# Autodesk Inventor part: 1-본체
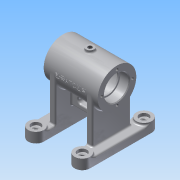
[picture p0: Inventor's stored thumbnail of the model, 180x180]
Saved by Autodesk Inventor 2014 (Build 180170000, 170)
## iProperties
Created: 2015-11
Part Number: 1-본체
Material: 알루미늄 6061
Document SubType Name: Modeling
Designer: 103-15
Density: 2.71 g/cm^3
Appearance: 알루미늄 - 평지
Mass: 357.75 g
Surface Area: 463.164 cm^2
Volume: 132.011 cm^3
Author: 103-15
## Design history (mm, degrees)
sketch "스케치1"
  geometry: L1 (-35, 0)-(35, 0); L2 (-35, 0)-(-35, 25); L3 (-35, 25)-(35, 25); L4 (35, 25)-(35, 0); L5 (-21, 0)-(-21, 21); L6 (-21, 21)-(21, 21); L7 (21, 21)-(21, 0); 3 further points
  constraints: 14 end point, 4 perpendicular, 2 midpoint, 2 parallel, 2 point on line, 1 coincident, 1 horizontal, 1 vertical alignment
  dimensions: "d0" = 70 distance of L1.start L1.end; "d1" = 50 diameter of L3 L1; "d16" = 42 diameter of L6 L1; "d17" = 42 distance between parallel lines of L7 L5
revolve "회전1" sketch "스케치1" stored, may be unused: angle "d2" = 90 deg
node "작업 평면1"
sketch "스케치2"
  geometry: L1 (30, -50)-(-30, -50); L2 (-40, -40)-(-40, 40); L3 (-30, 50)-(30, 50); L4 (40, 40)-(40, -40); L5 (40, -50)-(-40, 50); L6 (-40, -50)-(40, 50); L7 (-20, 40)-(-20, -40); L8 (20, -40)-(20, 40); A1 r 10 centre (-30, 40) between (-40, 40) and (-30, 50); A2 r 10 centre (-30, -40) between (-30, -50) and (-40, -40); A3 r 10 centre (30, -40) between (40, -40) and (30, -50); A4 r 10 centre (30, 40) between (30, 50) and (40, 40); 1 further point
  constraints: 16 end point, 12 point on circle, 11 tangent, 8 point on line, 4 centre point, 3 equal radius, 3 parallel, 2 midpoint, 1 horizontal, 1 perpendicular
  dimensions: "d4" = 100 distance of L6.start L5.end; "d5" = 80 distance of L5.start L6.start; "d6" = 10 radius of A1
extrude "돌출1" join sketch "스케치2" distance "d7" = 10; taper "d8" = 0 deg
extrude "돌출2" join sketch "스케치2" distance "d9" = 13; taper "d10" = 0 deg
node "작업 평면3"
sketch "스케치3"
  geometry: L1 (0, 10)-(80, 10) reference; L2 (15, 68)-(15, 10); L3 (65, 68)-(65, 10); A1 r 25 centre (40, 68) between (15, 68) and (65, 68) reference; 1 further point
  constraints: 4 end point, 2 perpendicular, 2 point on circle, 2 point on line, 2 tangent
extrude "돌출3" join sketch "스케치3" distance "d12" = 8; taper "d13" = 0 deg
node "작업 평면4"
hole "구멍1" diameter "d20" = 28; stored, may be unused: countersink angle "d24" = 90 deg, drill point angle "d26" = 118 deg; dims "d18" = 10, "d19" = 10, "d21" = 6, "d22" = 32, "d23" = 12, "d25" = 8
sketch "스케치4"
  geometry: C1 r 16 at (0, 0) reference; 1 further point
  constraints: 1 horizontal alignment
  dimensions: "d27" = 20 distance of C1.centre point (-20, 0)
hole "구멍2" sketch "스케치4" at (-20, 0) diameter "d28" = 3.242; stored, may be unused: countersink angle "d32" = 90 deg, drill point angle "d34" = 118 deg; dims "d29" = 8, "d30" = 32, "d31" = 12, "d33" = 10
node "작업 평면5"
sketch "스케치5"
  geometry: C1 r 10 at (0, 0) reference; C2 r 10 at (-60, 80) reference; C3 r 10 at (0, 80) reference; C4 r 10 at (-60, 0) reference; 5 further points
  constraints: 4 coincident
hole "구멍3" sketch "스케치5" at (-60, 80), (0, 80), (-60, 0), (0, 0) diameter "d39" = 6; stored, may be unused: countersink angle "d43" = 90 deg, drill point angle "d45" = 118 deg; dims "d40" = 8, "d41" = 12, "d42" = 4, "d44" = 10
node "작업 평면6"
sketch "스케치6"
  geometry: C1 r 5 at (0, 0); 1 further point
  constraints: 1 centre point, 1 coincident
  dimensions: "d47" = 10 diameter of C1
extrude "돌출4" join sketch "스케치6" stored distance "d48" = 8; taper "d49" = 0 deg
hole "구멍4" diameter "d52" = 5.188; stored, may be unused: countersink angle "d56" = 90 deg, drill point angle "d58" = 118 deg; dims "d53" = 8, "d54" = 6, "d55" = 4, "d57" = 10, "d59" = 10, "d60" = 10
node "작업 평면7"
sketch "스케치7"
  geometry: L1 (35, -25)-(-35, -25) reference; L2 (-20, 0)-(-20, -58) reference; L3 (-28, -58)-(-20, -58) reference; L4 (-28, 0)-(-28, -58) reference; L5 (-20, 0)-(-28, 0) reference; L6 (20, 0)-(20, -58) reference; L7 (-20, -45)-(20, -45); L8 (-20, -45)-(-20, -22.036); L9 (-20, -22.036)-(20, -22.036); L10 (20, -45)-(20, -22.036); L11 (-8, -31.5)-(8, -31.5); L12 (8, -38.5)-(-8, -38.5); L13 (33, -68)-(27, -68) reference; A1 r 3.5 centre (-8, -35) between (-8, -31.5) and (-8, -38.5); A2 r 3.5 centre (8, -35) between (8, -38.5) and (8, -31.5); 2 further points
  constraints: 12 end point, 4 point on circle, 4 point on line, 3 perpendicular, 2 centre point, 2 tangent, 1 collinear, 1 equal radius, 1 horizontal alignment, 1 midpoint, 1 parallel, 1 vertical alignment
  dimensions: "d62" = 20 distance between parallel lines of L7 L1; "d63" = 22.96425 distance between parallel lines of L7 L9; "d64" = 3.5 radius of A1; "d65" = 23 dimension on A2 A1; "d66" = 33 distance from line of L13 A2.centre
extrude "돌출5" join sketch "스케치7" stored distance "d67" = 8; taper "d68" = 0 deg
node "작업 평면8"
sketch "스케치8"
  geometry: L1 (0, 0)-(0, -25); L2 (0, 0)-(14, -24.249); 1 further point
  constraints: 4 end point, 1 vertical, 1 vertical alignment, 1 other
  dimensions: "d70" = 28 distance of L1.start L2.end; "d71" = 30 deg angle of L2 L1
node "작업 평면9"
sketch "스케치9"
  geometry: C1 r 6 at (0, 0); 1 further point
  constraints: 1 centre point, 1 coincident
  dimensions: "d72" = 12 diameter of C1
extrude "돌출6" join sketch "스케치9" stored distance "d73" = 8; taper "d74" = 0 deg
hole "구멍5" diameter "d77" = 5.188; stored, may be unused: countersink angle "d81" = 90 deg, drill point angle "d83" = 118 deg; dims "d75" = 10, "d76" = 10, "d78" = 8, "d79" = 6, "d80" = 4, "d82" = 10
node "작업 평면10"
sketch "스케치10"
  geometry: 2 further points
  constraints: 1 coincident, 1 other
feature "엠보싱1" sketch "스케치10" dims "d0" = 70, "d84" = 0.5, "d85" = 0
chamfer "모따기1" distance "d86" = 1; stored, may be unused: second distance "d87" = 2, angle "d88" = 45 deg
fillet "모깎기1" dims "d89" = 0.3, "d90" = 2
fillet "모깎기3" dims "d92" = 2
fillet "모깎기4" dims "d93" = 2
node "솔리드1"
mirror "대칭1"
pattern_circular "원형 패턴1" dims angle "d36" = 360 deg
mirror "대칭2"
node "투영된 루프1"
node "투영된 루프2"
node "투영된 루프3"
other parameters: "d3" = -68, "d11" = 0, "d14" = 0, "d38" = 0, "d46" = -96, "d61" = 0, "d69" = 0
